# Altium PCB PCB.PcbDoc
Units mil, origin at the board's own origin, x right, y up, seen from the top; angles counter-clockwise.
Board outline 2500.28 x 2690 mil, 4 copper layers (Top Layer, GND, Power, Bottom Layer), stack 79.834 mil thick; 90 components, 42 nets, 225 pads, 112 vias.
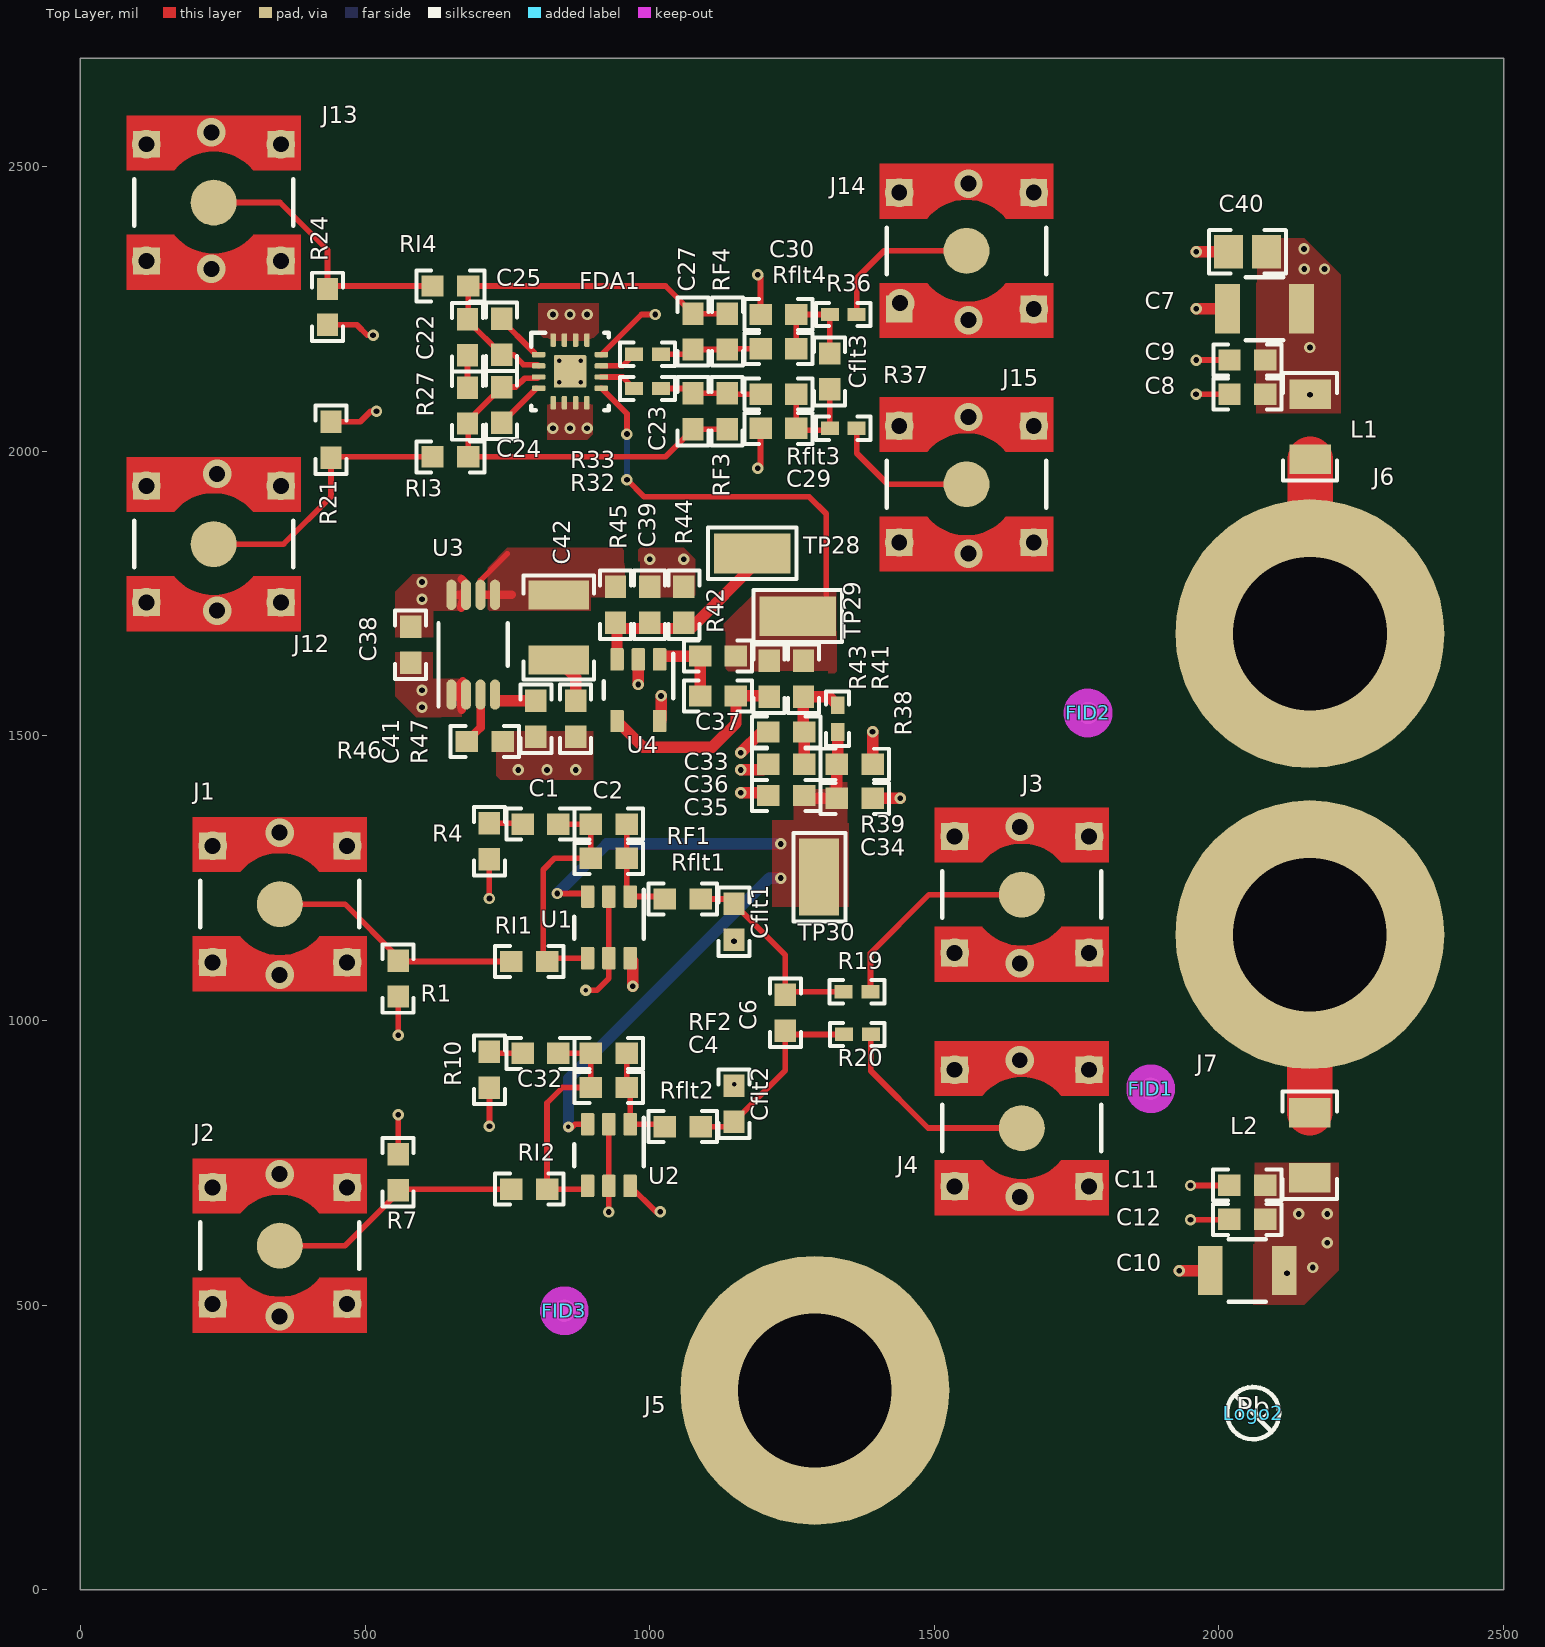
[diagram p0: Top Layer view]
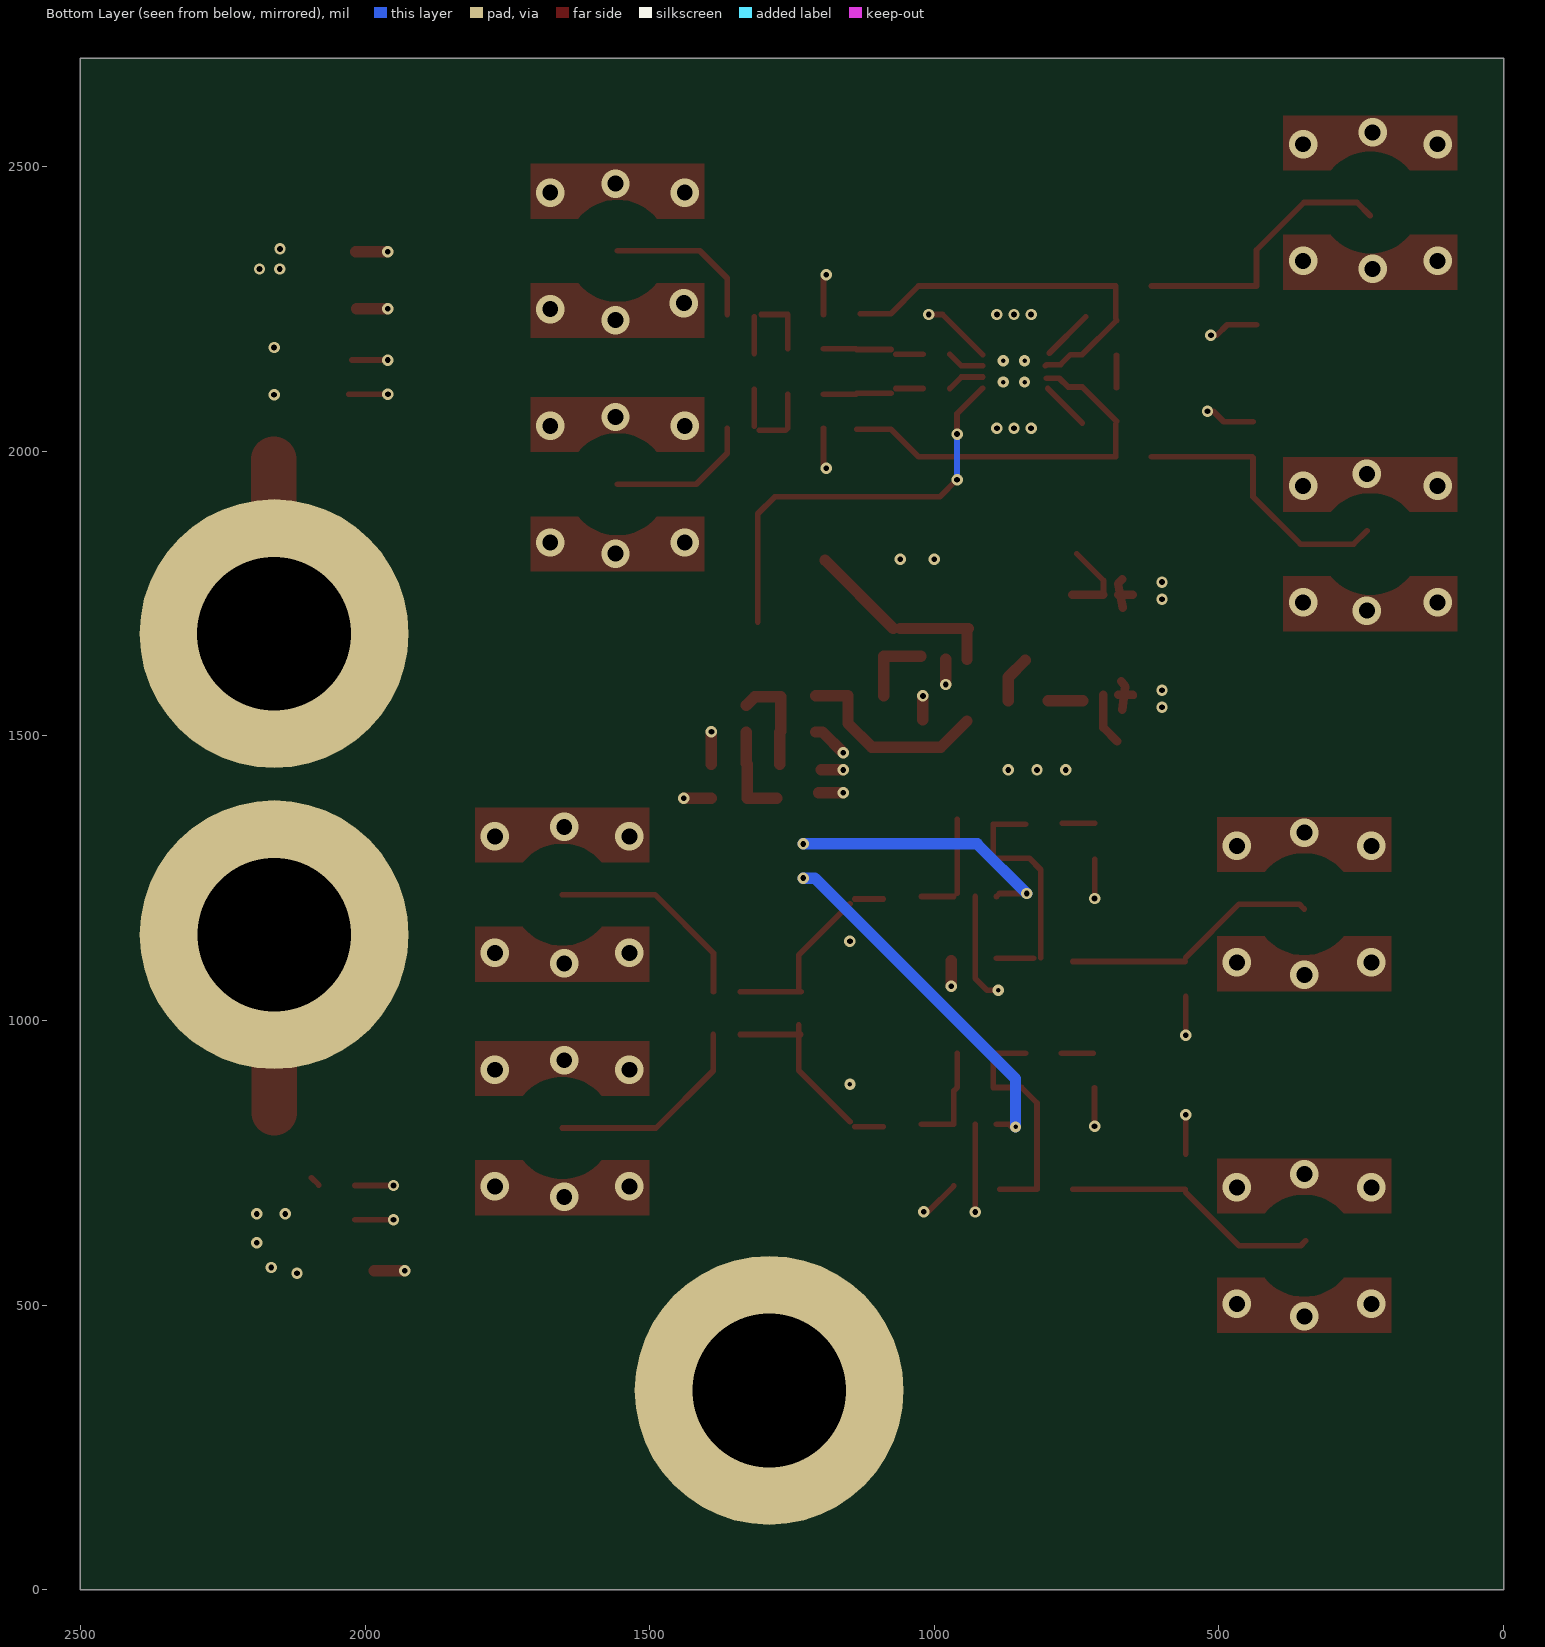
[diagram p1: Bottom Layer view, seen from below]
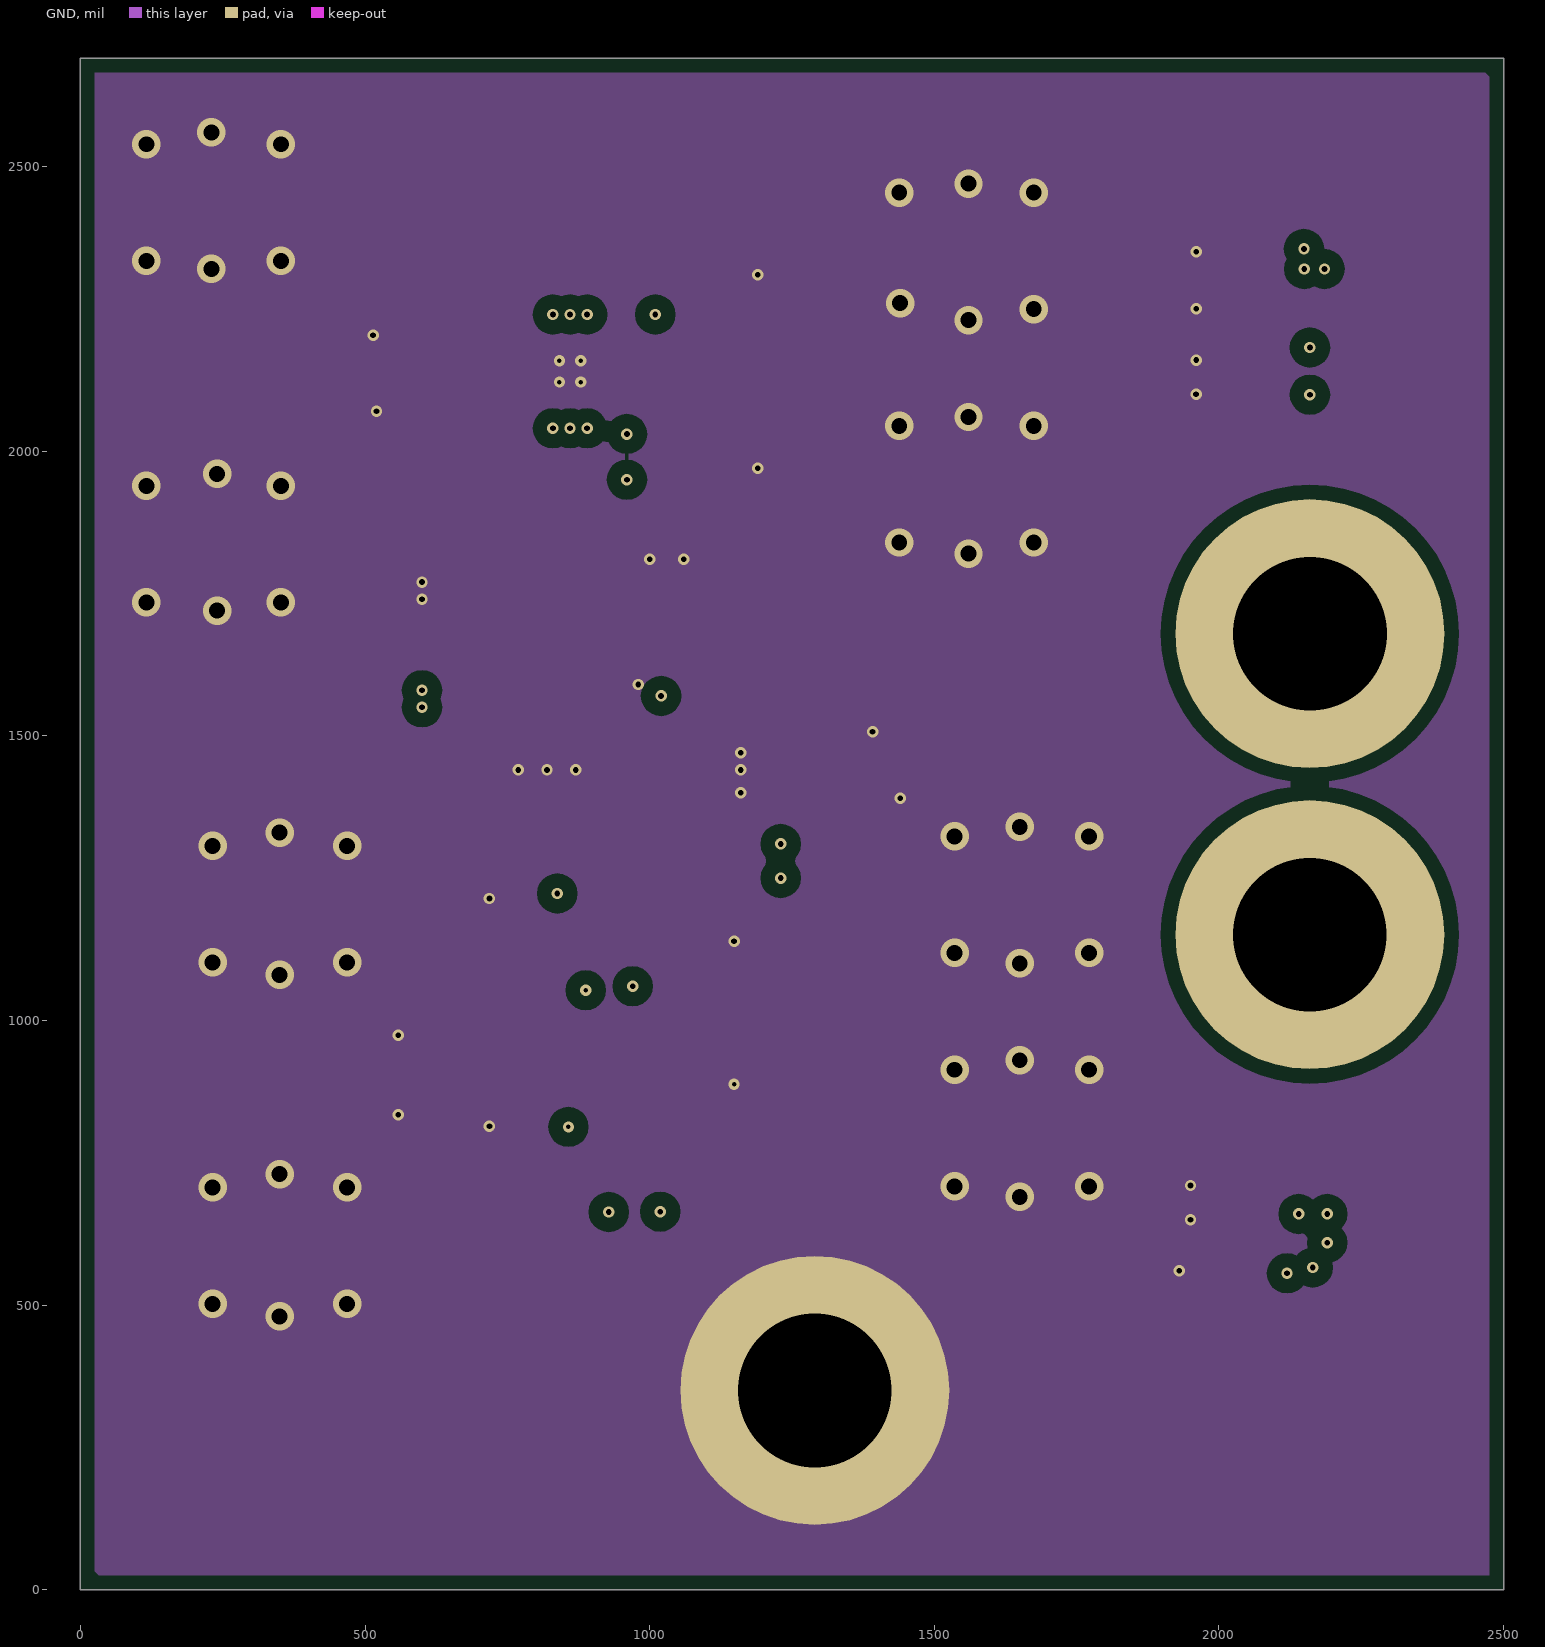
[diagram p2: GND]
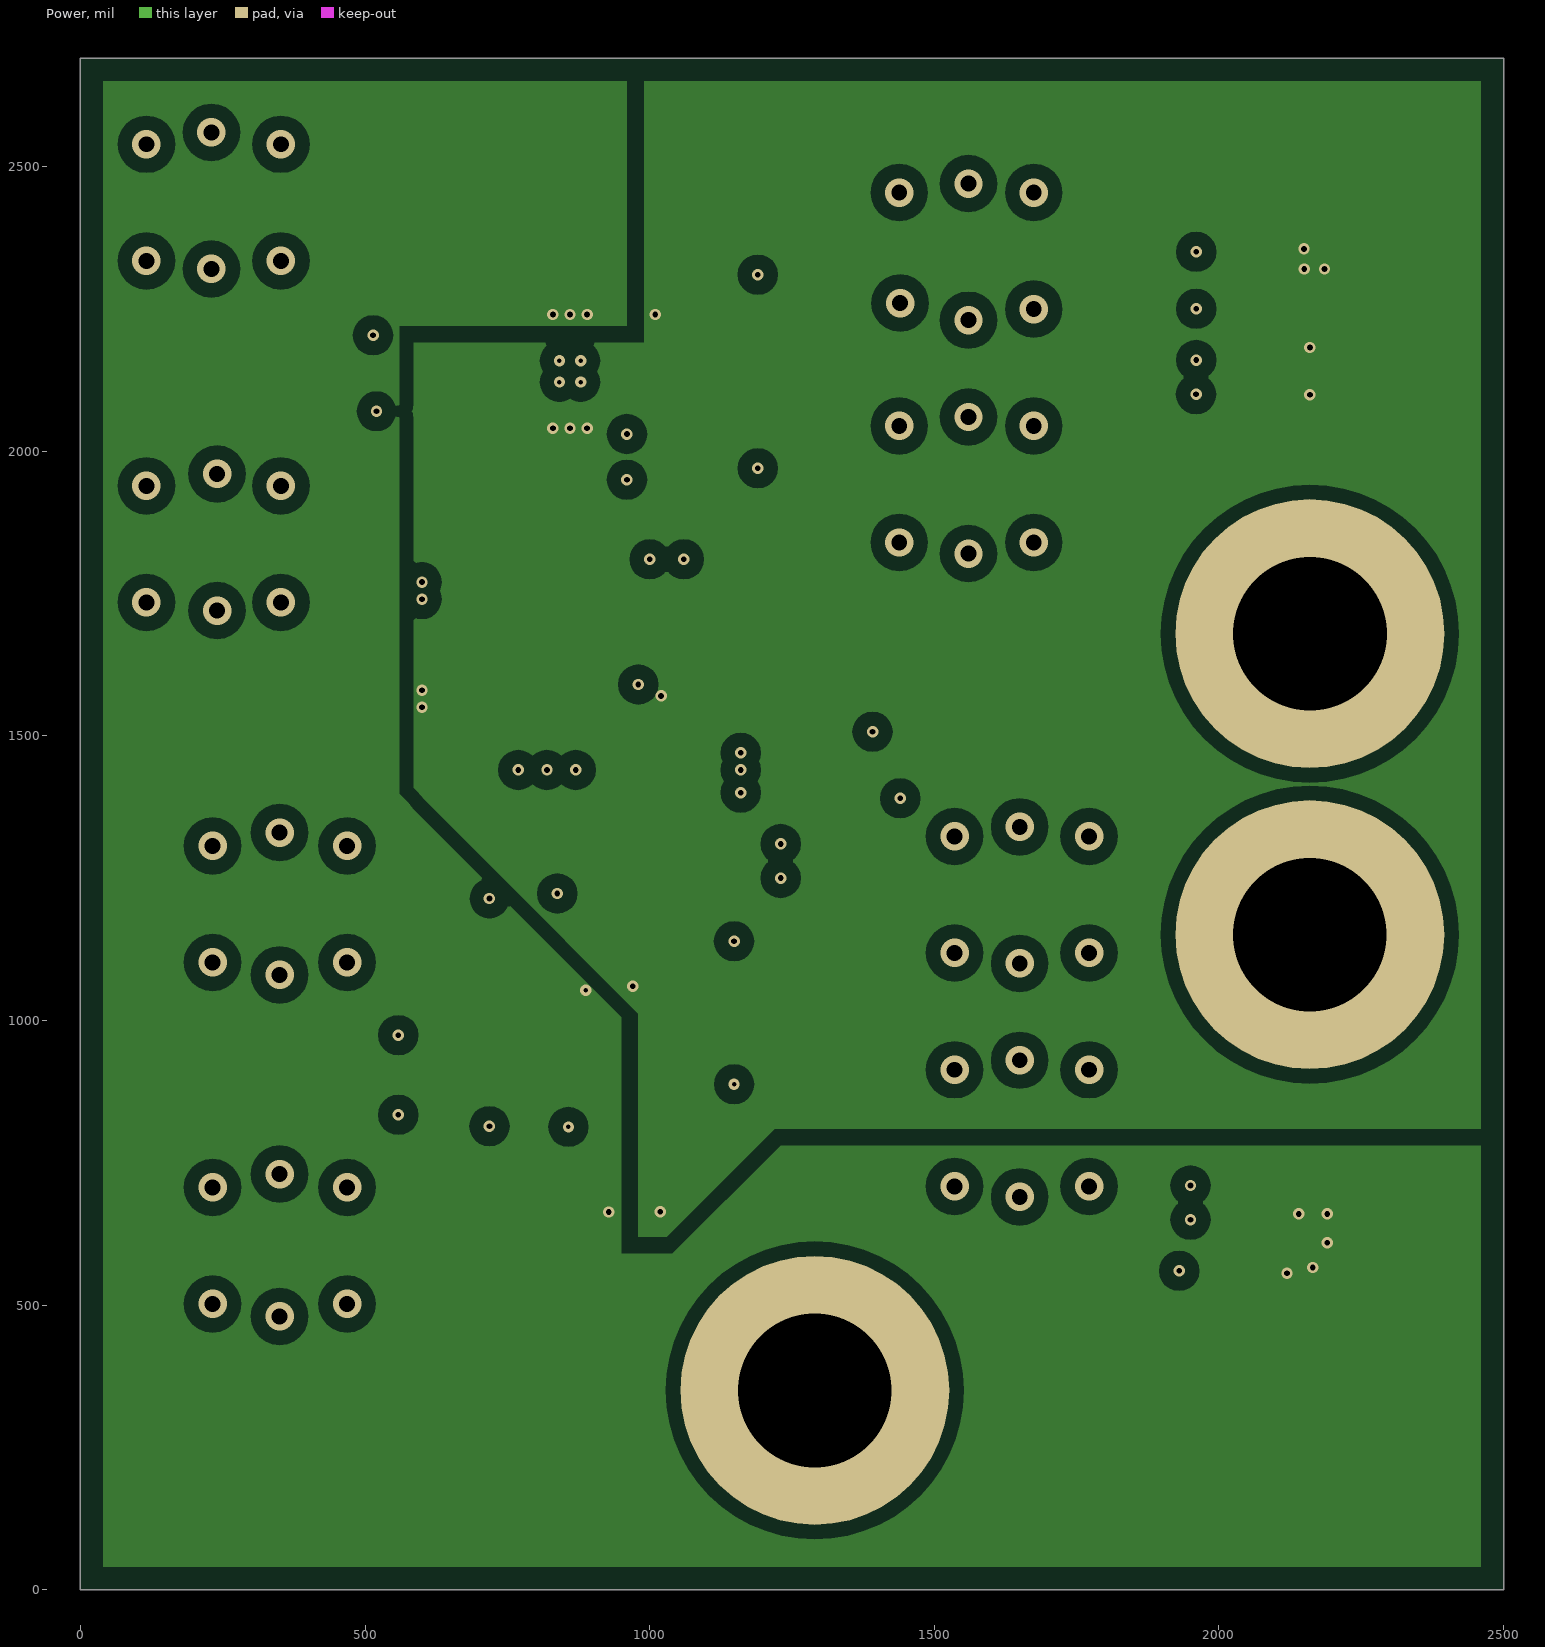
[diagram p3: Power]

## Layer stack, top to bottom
Top Solder: solder mask 0.4, Solder Resist, Dk 3.5
Top Layer: signal copper 1.4
Dielectric1: core 59.2, FR-4, Dk 4.8
GND: signal copper 1.417
Dielectric 3: prepreg 5, Dk 4.2
Power: signal copper 1.417
Dielectric 2: core 10, Dk 4.2
Bottom Layer: signal copper 1.4
Bottom Solder: solder mask 0.4, Solder Resist, Dk 3.5

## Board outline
-0.18,0 2499.89,0 2500.1,2690 0.05,2690

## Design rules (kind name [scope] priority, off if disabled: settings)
AcuteAngle [All] p1: minimum=4.50000000000000E+0001 checktracksonly=FALSE
AssemblyTestPointUsage [All] p1: valid=2
BoardOutlineClearance BoardOutlineClearance_MountingHoles [OnCopper and InComponentClass('Mounting Holes')] p1: gap=40
BoardOutlineClearance BoardOutlineClearance_Poly [OnCopper and IsPoly] p2: gap=25
BoardOutlineClearance [OnCopper and Not InComponentClass('Logo') and not InComponentClass('FiducialMark') and not InRegion(1000,500,4000,800) and not InPoly] p3: gap=75
Clearance Clearance_Keepouts [((IsTrack Or IsArc) And Not InPoly) And IsFree and IsKeepOut vs ((IsTrack Or IsArc) And Not InPoly) And IsFree and IsKeepOut] p1: gap=0
Clearance Clearance_Poly [InPolygon] p2: gap=25
Clearance [All] p3: gap=7.87
ComponentClearance ComponentClearance_MountingHoles_FiducialMarks [InComponentClass('Mounting Holes') vs InComponentClass('FiducialMark')] p1: gap=50 collisioncheckmode=3 verticalgap=10 showdistances=FALSE
ComponentClearance ComponentClearance_Shunt [InComponentClass('Header') vs InComponentClass('Shunt')] p2: gap=0 collisioncheckmode=3 verticalgap=0 showdistances=FALSE
ComponentClearance ComponentClearance_Logo [InComponentClass('Logo')] p3: gap=50 collisioncheckmode=3 verticalgap=10 showdistances=FALSE
ComponentClearance ComponentClearance_ScrewToNut [(HasFootprint('NY PMS 440 0025 PH')) vs (HasFootprint('Keystone_1902C'))] p4: gap=5 collisioncheckmode=3 verticalgap=10 showdistances=FALSE
ComponentClearance ComponentClearance_MountingHoles [InComponentClass('Mounting Holes')] p5: gap=250 collisioncheckmode=3 verticalgap=100000 showdistances=FALSE
ComponentClearance ComponentClearance_SmallPassives [HasFootprint('0201*') or HasFootprint('0402*') or HasFootprint('0508') or HasFootprint('0603*') or HasFootprint('0612') or HasFootprint('0805*') or HasFootprint('0815*') or HasFootprint('0830*') or HasFootprint('1206*') or HasFootprint('1210*') or HasFootprint('1808*') or HasFootprint('1812*') or HasFootprint('1825*') or HasFootprint('2010*') or HasFootprint('2220*') or HasFootprint('2225*') or HasFootprint('2512*') or HasFootprint('2728*') or HasFootprint('3518*') vs HasFootprint('0201*') or HasFootprint('0402*') or HasFootprint('0508') or HasFootprint('0603*') or HasFootprint('0612') or HasFootprint('0805*') or HasFootprint('0815*') or HasFootprint('0830*') or HasFootprint('1206*') or HasFootprint('1210*') or HasFootprint('1808*') or HasFootprint('1812*') or HasFootprint('1825*') or HasFootprint('2010*') or HasFootprint('2220*') or HasFootprint('2225*') or HasFootprint('2512*') or HasFootprint('2728*') or HasFootprint('3518*')] p6: gap=14.96 collisioncheckmode=3 verticalgap=10 showdistances=FALSE
ComponentClearance ComponentClearance_THtoSMT [IsThruComponent vs IsSMTComponent] p7: gap=40 collisioncheckmode=3 verticalgap=30 showdistances=FALSE
ComponentClearance ComponentClearance_THtoTH [IsThruComponent vs IsThruComponent] p8: gap=30 collisioncheckmode=3 verticalgap=30 showdistances=FALSE
ComponentClearance [All] p9: gap=30 collisioncheckmode=3 verticalgap=10 showdistances=FALSE
DiffPairsRouting [All] p1: maxlimit=100 minlimit=10 mostfreqgap=10 toplayer_minwidth=15 toplayer_maxwidth=15 toplayer_prefwidth=15 midlayer1_minwidth=15 midlayer1_maxwidth=15 midlayer1_prefwidth=15 midlayer2_minwidth=15 midlayer2_maxwidth=15 midlayer2_prefwidth=15 bottomlayer_minwidth=15 bottomlayer_maxwidth=15 bottomlayer_prefwidth=15 maxuncoupledlength=1000
FabricationTestPointUsage TestPointUsage [All] p1: valid=2 allowmultiple=FALSE
FabricationTestpoint Testpoint [All] p1: side=3 testpointundercomponent=TRUE minsize=40 maxsize=100 preferedsize=60 minholesize=0 maxholesize=40 preferedholesize=32 testpointgrid=1 allowsidetop=TRUE allowsidebottom=TRUE usegrid=TRUE gridtolerance=0.01
FanoutControl Fanout_LCC [IsLCC] p1: bgadir=Out bgaviamode=Centered fanoutstyle=Auto fanoutdirection=Alternating viagrid=1 // Fanout_LCC (Default Rule)
FanoutControl Fanout_BGA [IsBGA] p2: bgadir=Out bgaviamode=Centered fanoutstyle=Auto fanoutdirection=Alternating viagrid=1 // Fanout_BGA (Default Rule)
FanoutControl Fanout_Default [All] p4: bgadir=Out bgaviamode=Centered fanoutstyle=Auto fanoutdirection=Alternating viagrid=1 // Fanout_Default (Default Rule)
FanoutControl Fanout_Small [(CompPinCount < 5)] p5: bgadir=Out bgaviamode=Centered fanoutstyle=Auto fanoutdirection=OutThenIn viagrid=1 // Fanout_Small (Default Rule)
HoleSize [All] p1: absolutevalues=TRUE maxlimit=280 minlimit=5 maxpercent=80.000 minpercent=20.000
MinimumAnnularRing MinimumAnnularRing_ThermalPadVias [IsVia and InAnyComponent] p1: minimumring=5.91
MinimumAnnularRing [All] p2: minimumring=5
MinimumSolderMaskSliver MinimumSolderMaskSliver_Logo [InComponentClass('Logo') vs InComponentClass('Logo')] p1: minsoldermaskwidth=0.7
MinimumSolderMaskSliver [All] p2: minsoldermaskwidth=3.94
PlaneConnect [All] p1: planeconnectstyle=Relief reliefexpansion=10 reliefentries=4 reliefconductorwidth=10 reliefairgap=10
PolygonConnect PolygonConnect_10 [All vs IsNamedPolygon('GND')] p1: connectstyle=Direct reliefconductorwidth=10 reliefentries=4 polygonreliefangle="90 Angle" airgapwidth=10
PolygonConnect PolygonConnect_9 [All] p2: connectstyle=Direct reliefconductorwidth=10 reliefentries=4 polygonreliefangle="90 Angle" airgapwidth=10
PolygonConnect PolygonConnect_8 [All vs IsNamedPolygon('GND')] p3: connectstyle=Direct reliefconductorwidth=10 reliefentries=4 polygonreliefangle="90 Angle" airgapwidth=10
PolygonConnect PolygonConnect_7 [All vs IsNamedPolygon('GND')] p4: connectstyle=Direct reliefconductorwidth=10 reliefentries=4 polygonreliefangle="90 Angle" airgapwidth=10
PolygonConnect PolygonConnect_6 [All vs IsNamedPolygon('GND')] p5: connectstyle=Direct reliefconductorwidth=10 reliefentries=4 polygonreliefangle="90 Angle" airgapwidth=10
PolygonConnect PolygonConnect_5 [All vs IsNamedPolygon('GND')] p6: connectstyle=Direct reliefconductorwidth=10 reliefentries=4 polygonreliefangle="90 Angle" airgapwidth=10
PolygonConnect PolygonConnect_4 [All vs IsNamedPolygon('GND')] p7: connectstyle=Direct reliefconductorwidth=10 reliefentries=4 polygonreliefangle="90 Angle" airgapwidth=10
PolygonConnect PolygonConnect_3 [All vs IsNamedPolygon('GND')] p8: connectstyle=Direct reliefconductorwidth=10 reliefentries=4 polygonreliefangle="90 Angle" airgapwidth=10
PolygonConnect PolygonConnect_2 [All vs IsNamedPolygon('GND')] p9: connectstyle=Direct reliefconductorwidth=10 reliefentries=4 polygonreliefangle="90 Angle" airgapwidth=10
PolygonConnect PolygonConnect_1 [All vs IsNamedPolygon('GND')] p10: connectstyle=Direct reliefconductorwidth=10 reliefentries=4 polygonreliefangle="90 Angle" airgapwidth=10
PolygonConnect [All] p11: connectstyle=Relief reliefconductorwidth=10 reliefentries=4 polygonreliefangle="90 Angle" airgapwidth=10
RoutingVias ThermalPadVias [IsVia and InAnyComponent] p1: holewidth=7.87 width=19.68 viastyle="Through Hole" minholewidth=7.87 minwidth=19.68 maxholewidth=12.99 maxwidth=23.62
RoutingVias [All] p2: holewidth=16 width=34 viastyle="Through Hole" minholewidth=5 minwidth=6 maxholewidth=40 maxwidth=65
SilkToBoardRegionClearance [Not ((IsComment or IsDesignator) And (Hide <> 'False')) and not InRegion(1000,500,4000,800)] p1:
SilkToSilkClearance SilkToSilkClearance_Pb-FreeLogo [(HasFootprint('Pb-Free_Overlay_Medium') OR HasFootprint('Pb-Free_Overlay_Small')) vs (HasFootprint('Pb-Free_Overlay_Medium') OR HasFootprint('Pb-Free_Overlay_Small'))] p1: silktosilkclearance=0
SilkToSilkClearance [All] p2: silktosilkclearance=4
SilkToSolderMaskClearance SilkToComponentPadClearance [IsPad and InAnycomponent] p1: minsilkscreentomaskgap=5 clearancetoexposedcopper=TRUE
SilkToSolderMaskClearance "Silk to Solder Mask Opening" [All] p2: minsilkscreentomaskgap=4 clearancetoexposedcopper=FALSE
SolderMaskExpansion [All] p1: expansion=1.97
Width [All] p1: maxlimit=100 minlimit=6 preferedwidth=10 checkconnectedcopper=TRUE
15 further rules are at their usual default settings.

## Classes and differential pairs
component class OPA625_VCA_Disto_Hardware: C1 C2 C4 C6 C7 C8 C9 C10 C11 C12 C32 C33 C34 C35 C36 C37 C38 C39 C40 C41 C42 Cflt1 Cflt2 FID1 FID2 FID3 J1 J2 J3 J4 J5 J6 J7 L1 L2 Logo2 R1 R4 R7 R10 R19 R20 R38 R39 R41 R42 R43 R44 R45 R46 R47 RF1 RF2 Rflt1 Rflt2 RI1 RI2 TP28 TP29 TP30 U1 U2 U3 U4
component class FiducialMark: FID1 FID2 FID3
component class THS4551_VCA_Disto_Hardware: C22 C23 C24 C25 C27 C29 C30 Cflt3 FDA1 J12 J13 J14 J15 R21 R24 R27 R32 R33 R36 R37 RF3 RF4 Rflt3 Rflt4 RI3 RI4

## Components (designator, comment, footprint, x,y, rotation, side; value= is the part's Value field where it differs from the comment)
C1 "GRM1885C2A131JA01D" 0603 808.19,1344.7 r0 top
C2 "GRM1885C2A5R0CA01D" 0603 928.19,1344.7 r180 top
C4 "GRM1885C2A5R0CA01D" 0603 928.19,882.11 r180 top
C6 "C1608C0G2A102J080AA" 0603 1238.19,1013.41 r270 top
C7 "UMK325AB7106KM-T" 1210_280 2080,2250 r180 top
C8 "GRM188R72A104KA35D" 0603 2050,2100 r180 top
C9 "GRM188R71E103KA01D" 0603 2050,2160 r180 top
C10 "UMK325AB7106KM-T" 1210_280 2049.65,560.57 r180 top
C11 "GRM188R72A104KA35D" 0603 2049.65,710.57 r180 top
C12 "GRM188R71E103KA01D" 0603 2049.65,650.57 r180 top
C22 "GRM1885C2A680JA01D" 0603 680,2200 r90 top
C23 "GRM1885C2A5R0CA01D" 0603 1076.2,2070 r270 top
C24 "C1608C0G2A102J080AA" 0603 740,2081.02 r90 top
C25 "C1608C0G2A102J080AA" 0603 740,2201.02 r270 top
C27 "GRM1885C2A5R0CA01D" 0603 1076.2,2210 r90 top
C29 "C1608C0G2A102J080AA" 0603 1226.2,2040 r180 top
C30 "C1608C0G2A102J080AA" 0603 1226.2,2240 r180 top
C32 "GRM1885C2A131JA01D" 0603 808.19,942.11 r0 top
C33 "C0603C104J3RACTU" 0603 1240,1506.64 r180 top
C34 "C0603C102J5GAC" 0603 1360,1390 r0 top
C35 "C0603C102J5GAC" 0603 1240,1394.96 r180 top
C36 "GRM188R71E105KA12D" 0603 1240,1450 r180 top
C37 "GRM188R71E105KA12D" 0603 1120,1570 r0 top
C38 "C0603C104J3RACTU" 0603 580,1660 r270 top
C39 "GRM188R71E105KA12D" 0603 1000,1730 r90 top
C40 "GRM21BR71A106KE51L" 0805 2050,2350 r0 top
C41 "GRM188R71A105KA61D" 0603 800,1530 r270 top
C42 "GRM32ER71A476KE15L" 1210_270 840,1690 r270 top
Cflt1 "C1608C0G2A102J080AA" 0603 1148.19,1173.41 r270 top
Cflt2 "C1608C0G2A102J080AA" 0603 1148.19,853.41 r90 top
Cflt3 "C1608C0G2A102J080AA" 0603 1316.2,2140 r90 top
FDA1 "THS4551IRGTR" RGT0016A 860,2140 r0 top
FID1 "Fiducial" Fiducial10-20 1880,880 r180 top
FID2 "Fiducial" Fiducial10-20 1770,1540 r0 top
FID3 "Fiducial" Fiducial10-20 850,490 r90 top
J1 "CONSMA001-SMD-G" Linx_CONSMA001-SMD-G 350.31,1204.21 r90 top
J2 "CONSMA001-SMD-G" Linx_CONSMA001-SMD-G 350.31,604.21 r90 top
J3 "CONSMA001-SMD-G" Linx_CONSMA001-SMD-G 1653.64,1220.89 r90 top
J4 "CONSMA001-SMD-G" Linx_CONSMA001-SMD-G 1653.64,810.89 r90 top
J5 "6095" Keystone_6095 1290,350 r0 top
J6 "6095" Keystone_6095 2159.76,1679.29 r0 top
J7 "6095" Keystone_6095 2159.65,1150.57 r180 top
J12 "CONSMA001-SMD-G" Linx_CONSMA001-SMD-G 234.01,1836.69 r270 top
J13 "CONSMA001-SMD-G" Linx_CONSMA001-SMD-G 234.01,2436.69 r90 top locked
J14 "CONSMA001-SMD-G" Linx_CONSMA001-SMD-G 1556.51,2351.87 r90 top
J15 "CONSMA001-SMD-G" Linx_CONSMA001-SMD-G 1556.51,1941.87 r90 top
L1 "MI1206K310R-10" 1206 2160,2042.76 r90 top
L2 "MI1206K310R-10" 1206 2159.65,780.57 r270 top
Logo2 "Pb-Free Symbol" Pb-Free_Overlay_Small 2060,310 r0 top
R1 "RC0603FR-0752R3L" 0603 558.19,1073.41 r270 top
R4 "RC0603FR-07124RL" 0603 718.19,1314.7 r90 top
R7 "RC0603FR-0752R3L" 0603 558.19,733.41 r90 top
R10 "RC0603FR-07124RL" 0603 718.19,913.41 r90 top
R19 "ERJ-2GE0R00X" 0402 1364.23,1050.56 r0 top
R20 "ERJ-2GE0R00X" 0402 1364.74,975.33 r0 top
R21 "RC0603FR-0752R3L" 0603 440,2020 r90 top
R24 "RC0603FR-0752R3L" 0603 434.01,2253.39 r270 top
R27 "CRCW0603249RFKEA" 0603 680,2080 r270 top
R32 "ERJ-2GE0R00X" 0402 996.2,2110 r0 top
R33 "ERJ-2GE0R00X" 0402 996.2,2170 r0 top
R36 "ERJ-2GE0R00X" 0402 1340,2240 r0 top
R37 "ERJ-2GE0R00X" 0402 1340,2040 r0 top
R38 "ERJ-2GE0R00X" 0402 1330,1530 r270 top
R39 "RT0603BRB071KL" 0603 1360,1450 r180 top
R41 "RT0603BRB071KL" 0603 1270,1600 r90 top
R42 "RG1608P-4990-B-T5" 0603 1120,1640 r0 top
R43 "RG1608P-203-B-T5" 0603 1210,1600 r90 top
R44 "RG1608P-4992-B-T5" 0603 1060,1730 r270 top
R45 "RG1608P-4992-B-T5" 0603 940,1730 r90 top
R46 "ERJ-3RQFR22V" 0603 710,1490 r180 top
R47 "ERJ-3RQFR22V" 0603 870,1530 r270 top
RF1 "RT0603BRB071KL" 0603 928.19,1284.7 r0 top
RF2 "RT0603BRB071KL" 0603 928.19,942.11 r0 top
RF3 "RT0603BRB071KL" 0603 1136.2,2070 r90 top
RF4 "RT0603BRB071KL" 0603 1136.2,2210 r270 top
Rflt1 "RT0603BRD0720RL" 0603 1058.19,1213.41 r0 top
Rflt2 "RT0603BRD0720RL" 0603 1058.19,813.41 r0 top
Rflt3 "RT0603BRD0720RL" 0603 1226.2,2100 r0 top
Rflt4 "RT0603BRD0720RL" 0603 1226.2,2180 r0 top
RI1 "RT0603BRB071KL" 0603 788.19,1103.41 r0 top
RI2 "RT0603BRB071KL" 0603 788.19,703.41 r0 top
RI3 "RT0603BRB071KL" 0603 650,1990 r0 top
RI4 "RT0603BRB071KL" 0603 650,2290 r0 top
TP28 "5015" Testpoint_Keystone_Miniature 1180,1820 r180 top
TP29 "5015" Testpoint_Keystone_Miniature 1260,1710 r180 top
TP30 "5015" Testpoint_Keystone_Miniature 1297.59,1251.61 r90 top
U1 "OPA625IDBVR" DBV0006A_N 928.19,1163.41 r270 top
U2 "OPA625IDBVR" DBV0006A_N 928.19,763.41 r270 top
U3 "REF6050IDGKR" DGK0008A_N 690,1660 r90 top
U4 "OPA376AIDBVR" DBV0005A_N 980,1580 r270 top

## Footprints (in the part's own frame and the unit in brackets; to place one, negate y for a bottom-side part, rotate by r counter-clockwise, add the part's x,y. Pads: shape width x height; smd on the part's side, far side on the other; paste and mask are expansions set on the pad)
0402 [mm] "0402 from SM-752 data"
  rect 0.8x0.6 smd: 1(-0.6,0) 2(0.6,0)
  silkscreen extent -1.22,-0.52 1.22,0.52, body extent -0.55,-0.3 0.55,0.3, height 0.6
0603 [mm] "0603 from SM-752 data"
  rect 1x0.95 smd: 1(-0.8,0) 2(0.8,0)
  silkscreen extent -1.52,-0.69 1.52,0.69, body extent -0.87,-0.47 0.87,0.47, height 1
0805 [mm] "0805 from SM-752 data"
  rect 1.3x1.5 smd: 1(-0.85,0) 2(0.85,0)
  silkscreen extent -1.72,-0.97 1.72,0.97, body extent -1.1,-0.72 1.1,0.72, height 1.45
1206 [mm] "1206 from SM-752 data"
  rect 1.3x1.85 smd: 1(-1.45,0) 2(1.45,0)
  silkscreen extent -2.4,-1.21 2.4,1.21, body extent -1.7,-0.9 1.7,0.9, height 1.35
1210_270 [mm] "1210"
  rect 1.3x2.7 smd: 1(-1.45,0) 2(1.45,0)
  silkscreen extent -2.32,-1.57 2.32,1.57, body extent -1.7,-1.35 1.7,1.35, height 2.7
1210_280 [mm] "SMD, 2-Leads, Body 3.6x2.8mm, Height 2.8mm"
  rect 1.1x2.2 smd: 1(-1.65,0) 2(1.65,0)
  silkscreen extent -0.84,-1.4 0.84,1.4, body extent -1.8,-1.4 1.8,1.4, height 2.8
DBV0005A_N [mm] "SOT23, 5-Leads, Body 2.9x1.6mm, Pitch 0.95mm, Lead Span 2.8mm, IPC Medium Density"
  rrect17% 1x0.6 smd: 1(-1.375,0.95) 2(-1.375,0) 3(-1.375,-0.95) 4(1.375,-0.95) 5(1.375,0.95)
  silkscreen extent -1.63,-1.55 0.38,1.55, body extent -1.42,-1.46 1.42,1.46, height 1.09
DBV0006A_N [mm] "SOT23, 6-Leads, Body 2.9x1.6mm, Pitch 0.95mm, Lead Span 2.8mm, IPC Medium Density"
  rrect17% 1x0.6 smd: 1(-1.375,0.95) 2(-1.375,0) 3(-1.375,-0.95) 4(1.375,-0.95) 5(1.375,0) 6(1.375,0.95)
  silkscreen extent -1.68,-1.55 0.5,1.55, body extent -1.42,-1.46 1.42,1.46, height 1.12
DGK0008A_N [mm] "TSOP, 8-Leads, Body 3x3mm, Pitch 0.65mm, IPC Medium Density"
  oval 1.35x0.45 smd: 1(-2.225,0.975) 2(-2.225,0.325) 3(-2.225,-0.325) 4(-2.225,-0.975) 5(2.225,-0.975) 6(2.225,-0.325) 7(2.225,0.325) 8(2.225,0.975)
  silkscreen extent -2.75,-1.55 0.95,1.55, body extent -2.45,-1.5 2.45,1.5, height 0.96
Fiducial10-20 [mm]
  round 1 smd mask+0.5: 1(0,0)
  Top Layer keep-out circle w1.178: c0,0 r0.5
Keystone_6095 [mm] "Banana Jack Uninsulated Standard Type"
  round 12 hole 6.858: 1(0,0)
  body extent -4.77,-5.5 4.75,5.49, height 2.39
Linx_CONSMA001-SMD-G [mm] "SMD, 5-Leads, Body 7x7mm, Height 10.5mm"
  round 2.05 smd: 1(0,0)
  rect 1.2x1.2 smd: 2(-2.6,-3) 3(2.6,-3) 4(2.6,3) 5(-2.6,3)
  Top Layer region: 3.88,-3.88 1.44,-3.88 1.44,-1.761 1.448,-1.761 2.062,-0.974 2.28,0 2.062,0.974 1.448,1.761 1.448,1.761 1.44,1.761 1.44,3.88 3.88,3.88
  Top Layer region: -3.88,-3.88 -1.44,-3.88 -1.44,-1.761 -1.448,-1.761 -2.062,-0.974 -2.28,0 -2.062,0.974 -1.448,1.761 -1.448,1.761 -1.44,1.761 -1.44,3.88 -3.88,3.88
  silkscreen extent -1.04,-3.55 1.04,3.55, body extent -3.55,-3.55 3.55,3.55, height 10.5
Pb-Free_Overlay_Small [mil]
  silkscreen extent -46,-46 46,46
RGT0016A [mm] "QFN, 16-Leads, Body 3x3mm, Pitch 0.5mm, Thermal Pad 1.45x1.45mm, TI Recommended"
  rrect42% 0.6x0.24 smd: 1(-1.4,0.75) 2(-1.4,0.25) 3(-1.4,-0.25) 4(-1.4,-0.75) 9(1.4,-0.75) 10(1.4,-0.25) 11(1.4,0.25) 12(1.4,0.75)
  rrect42% 0.24x0.6 smd: 5(-0.75,-1.4) 6(-0.25,-1.4) 7(0.25,-1.4) 8(0.75,-1.4) 13(0.75,1.4) 14(0.25,1.4) 15(-0.25,1.4) 16(-0.75,1.4)
  rrect7% 1.45x1.45 smd paste-0.725: 17(0,0)
  silkscreen extent -1.72,-1.73 1.72,1.73, body extent -1.57,-1.57 1.58,1.58, height 1.01
Testpoint_Keystone_Miniature [mil] "Miniature SMT test point"
  rect 135x70 smd: 1(0,0)
  silkscreen extent -78,-46 78,45, body extent -52,-20 52,20, height 61

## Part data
C1 C32: "CAP, CERM, 130 pF, 100 V, +/- 5%, C0G/NP0, 0603"
C2 C4 C23 C27: "CAP, CERM, 5 pF, 100 V, +/- 5%, C0G/NP0, 0603"
C6 C24 C25 C29 C30 Cflt1 Cflt2 Cflt3: "CAP, CERM, 1000 pF, 100 V, +/- 5%, C0G/NP0, 0603"
C7 C10: "CAP, CERM, 10 µF, 50 V, +/- 10%, X7R, 1210"
C8 C11: "CAP, CERM, 0.1 µF, 100 V, +/- 10%, X7R, 0603"
C9 C12: "CAP, CERM, 0.01 µF, 25 V, +/- 10%, X7R, 0603"
C22: "CAP, CERM, 68 pF, 100 V, +/- 5%, C0G/NP0, 0603"
C33 C38: "CAP, CERM, 0.1 µF, 25 V, +/- 5%, X7R, 0603"
C34 C35: "CAP, CERM, 1000 pF, 50 V, +/- 5%, C0G/NP0, 0603"
C36 C37 C39: "CAP, CERM, 1 µF, 25 V, +/- 10%, X7R, 0603"
C40: "CAP, CERM, 10uF, 10V, +/-10%, X7R, 0805"
C41: "CAP, CERM, 1uF, 10V, +/-10%, X7R, 0603"
C42: "CAP, CERM, 47 µF, 10 V, +/- 10%, X7R, 1210"
FDA1: "Low Power, Precision, 160MHz, Fully Differential Amplifier, RGT0016A"
FID1 FID2 FID3: "Fiducial mark.  There is nothing to buy or mount."
J1 J2 J3 J4 J12 J13 J14 J15: "Jack, SMA, PCB, Gold, SMT"
J5 J6 J7: "Standard Banana Jack, Uninsulated"
L1 L2: "Ferrite Bead, 31 ohm @ 100 MHz, 1.5 A, 1206"
Logo2: library part Pb-Free
R1 R7 R21 R24: "RES, 52.3, 1%, 0.1 W, 0603"
R4 R10: "RES, 124, 1%, 0.1 W, 0603"
R19 R20 R32 R33 R36 R37 R38: "RES, 0, 5%, 0.063 W, 0402"
R27: "RES, 249, 1%, 0.1 W, 0603"
R39 R41 RF1 RF2 RF3 RF4 RI1 RI2 RI3 RI4: "RES, 1.00 k, 0.1%, 0.1 W, 0603"
R42: "RES, 499, 0.1%, 0.1 W, 0603"
R43: "RES, 20.0 k, 0.1%, 0.1 W, 0603"
R44 R45: "RES, 49.9 k, 0.1%, 0.1 W, 0603"
R46 R47: "RES, 0.22 ohm, 1%, 0.1W, 0603"
Rflt1 Rflt2 Rflt3 Rflt4: "RES, 20.0, 0.1%, 0.1 W, 0603"
TP28 TP29 TP30: "Test Point, Miniature, SMT"
U1 U2: "High Bandwidth, High Precision, Low Noise and Distortion Amplifier with Ultra-Fast Transition time Low Power mode, DBV0006A (SOT-6)"
U3: "High-Precision Voltage Reference with Integrated High-Bandwidth Buffer, DGK0008A (VSSOP-8)"
U4: "Precision, Low Noise, Low Iq Operational Amplifier, 2.2 to 5.5 V, -40 to 125 degC, 5-pin SOT23 (DBV0005A), Green (RoHS & no Sb/Br)"

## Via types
v1: diameter 20, hole 10, Top Layer to Bottom Layer, 57 vias
v2: diameter 50, hole 28, Top Layer to Bottom Layer, 48 vias
v3: diameter 19.68, hole 7.87, Top Layer to Bottom Layer, 7 vias

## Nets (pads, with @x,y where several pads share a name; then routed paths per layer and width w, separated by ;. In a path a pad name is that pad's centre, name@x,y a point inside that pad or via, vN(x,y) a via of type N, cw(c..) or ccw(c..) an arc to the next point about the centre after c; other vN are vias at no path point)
GND: C7.2 C8.2 C9.2 C10.2 C11.2 C12.2 C29.2 C30.2 C33.2 C34.2 C35.2 C36.2 C38.1 C39.2 C40.1 C41.2 Cflt1.2 Cflt2.2 FDA1.17 J1.2 J1.3 J1.4 J1.5 J2.2 J2.3 J2.4 J2.5 J3.2 J3.3 J3.4 J3.5 J4.2 J4.3 J4.4 J4.5 J5.1 J12.2 J12.3 J12.4 J12.5 J13.2 J13.3 J13.4 J13.5 J14.2 J14.3 J14.4 J14.5 J15.2 J15.3 J15.4 J15.5 R1.2 R4.1 R7.2 R10.1 R21.2 R24.2 R39.1 R44.1 R46.1 R47.2 U3.7 U3.8 U4.2 | length 1375.8
  Top Layer w10: R24.2 485.51,2221.89 504.01,2203.39 v1(514.01,2203.39) ; R21.2 491.5,2051.5 510,2070 v1(520,2070) ; v1@558.19,974.35 R1.2 ; R7.2@558.43,765.14 v1(558.43,834.11) ; 718.19,1224.35 R4.1 ; v1(718.43,814.11) R10.1@718.43,881.67 ; v1@1194.7,1974.7 C29.2 ; C30.2 v1@1194.7,2305.3 ; v1(1950,650) C12.2@2017.58,650 ; v1(1950,710) C11.2@2017.58,710 ; v1(1959.8,2100) C8.2@2028.74,2100 ; v1@1959.8,2160 C9.2@2022.74,2160
  Top Layer w15: U3.8 U3.7 ; 669.29,1725 677.2,1767.38 669.99,1774.6
  Top Layer w20: v1(980,1590) U4.2 ; v1(1160,1400) C35.2@1203.47,1400 ; v1(1160,1440) C36.2@1198.5,1440 ; v1(1160,1470) 1196.64,1506.64 C33.2 ; C34.2 v1(1440,1390) ; R39.1 v1(1391.5,1507.01) ; v1(1930,560) C10.2@1984.12,560 ; v1(1960,2250) C7.2 ; v1(1960,2350) C40.1
  other v1: 558.43,974.11 1148.19,1138.98 718.43,1214.11 769.14,1440 819.57,1440 870,1440 600,1740 600,1770 1000,1810 1060,1810 1190,1970 1960,2160 1190,2310
  other v2: 350,480 232.2,501.85 468.42,501.85 1650,690 232.2,706.57 468.42,706.57 1535.53,708.52 1771.75,708.52 350,730 1535.53,913.25 1771.75,913.25 1650,930 350,1080 1650,1100 232.2,1101.85 468.42,1101.85 1535.53,1118.52 1771.75,1118.52 232.2,1306.57 468.42,1306.57 1535.53,1323.25 1771.75,1323.25 350,1330 1650,1340 240,1720 115.9,1734.33 352.12,1734.33 1560,1820 1438.4,1839.51 1674.62,1839.51 115.9,1939.06 352.12,1939.06 240,1960 1438.4,2044.24 1674.62,2044.24 1560,2060 1560,2230 1674.62,2249.51 1440,2260 230,2320 115.9,2334.33 352.12,2334.33 1438.4,2454.23 1674.62,2454.23 1560,2470 115.9,2539.06 352.12,2539.06 230,2560
  other v3: 1148.19,887.85 841.3,2121.3 878.7,2121.3 841.3,2158.7 878.7,2158.7
NetC1_1: C1.1 R4.2 | length 57
  Top Layer w10: R4.2 C1.1@775.2,1346.2
NetC1_2: C1.2 C2.2 RF1.1 RI1.2 U1.4 | length 428.7
  Top Layer w10: RI1.2@812.84,1110.25 812.84,1264.55 833,1284.7 RF1.1 C2.2 C1.2 ; RI1.2@825.55,1109.27 U1.4
NetC2_1: C2.1 RF1.2 Rflt1.1 U1.1 | length 186.9
  Top Layer w10: U1.1@959.69,1223.44 C2.1 C2.1@959.69,1353.41 ; U1.1 Rflt1.1@1022.56,1217.54
NetC4_1: C4.1 RF2.2 Rflt2.1 U2.1 | length 184
  Top Layer w10: RF2.2 C4.1 965.59,876.2 U2.1 Rflt2.1@1022.56,817.54
NetC4_2: C4.2 C32.2 RF2.1 RI2.2 U2.4 | length 422
  Top Layer w10: C32.2 RF2.1 C4.2 846.89,882.11 819.69,854.9 RI2.2 U2.4@884.92,703.41
NetC6_1: C6.1 Cflt1.1 R19.1 Rflt1.2 | length 343.7
  Top Layer w10: Rflt1.2 Cflt1.1@1139.69,1213.41 ; Cflt1.1 1238.19,1114.9 C6.1@1238.19,1054.9 ; C6.1@1234.23,1050.56 R19.1
NetC6_2: C6.2 Cflt2.1 R20.1 Rflt2.2 | length 363.7
  Top Layer w10: Rflt2.2 Cflt2.1@1139.69,813.41 ; Cflt2.1 1238.19,911.91 C6.2 C6.2@1238.19,991.91 ; C6.2@1234.74,975.33 R20.1
NetC22_1: C22.1 R27.1 | length 57
  Top Layer w10: R27.1 C22.1
NetC22_2: C22.2 C25.2 C27.2 FDA1.2 RF4.1 RI4.2 | length 683.5
  Top Layer w10: C22.2@680,2229.53 C25.2 760.47,2169.53 778.07,2151.93 802.8,2151.93 FDA1.2 ; C22.2@681.5,2232.99 RI4.2 1027.7,2290 C27.2 RF4.1@1130,2241.5
NetC23_1: C23.1 R32.2 RF3.2 Rflt3.1 | length 164.9
  Top Layer w10: R32.2 C23.1@1067.7,2110 ; C23.1 RF3.2 ; RF3.2@1137.7,2100 Rflt3.1
NetC23_2: C23.2 C24.2 FDA1.3 R27.2 RF3.1 RI3.2 | length 685.9
  Top Layer w10: R27.2@680,2052.52 C24.2 764.8,2112.52 780.35,2128.07 FDA1.3@802.8,2128.07 ; R27.2@681.5,2047.01 RI3.2 1027.7,1990 C23.2 RF3.1
NetC24_1: C24.1 FDA1.4 | length 85.8
  Top Layer w10: C24.1 FDA1.4@800.67,2110.2
NetC25_1: C25.1 FDA1.1 | length 90.4
  Top Layer w10: C25.1@734.09,2235.83 FDA1.1@798.03,2171.89
NetC27_1: C27.1 R33.2 RF4.2 Rflt4.1 | length 164.9
  Top Layer w10: R33.2 C27.1@1067.7,2170 ; C27.1 RF4.2 ; RF4.2@1137.7,2180 Rflt4.1
NetC29_1: C29.1 Cflt3.1 R37.1 Rflt3.2 | length 170.8
  Top Layer w10: C29.1 Rflt3.2 ; C29.1@1261.24,2036.46 R37.1@1307.34,2036.46 ; R37.1@1316.2,2043.8 Cflt3.1
NetC30_1: C30.1 Cflt3.2 R36.1 Rflt4.2 | length 170.8
  Top Layer w10: Rflt4.2 C30.1 R36.1@1303.8,2240 ; Cflt3.2 R36.1@1316.2,2236.2
NetC32_1: C32.1 R10.2 | length 55.7
  Top Layer w10: R10.2@720.98,942.11 C32.1
NetC37_1: C37.1 R42.1 U4.1 | length 135.2
  Top Layer w20: U4.1@1023.27,1640 R42.1 C37.1
NetC37_2: C37.2 R43.1 U4.4 | length 350.6
  Top Layer w20: U4.4 988.46,1480 1110,1480 1151.5,1521.5 C37.2 R43.1@1208.5,1570
NetC39_1: C39.1 R44.2 R45.1 TP28.1 U4.3 | length 341.5
  Top Layer w20: R45.1@940,1688.5 1000,1688.5 R44.2@1060,1688.5 ; U4.3 R45.1@942.6,1685.91 ; R44.2@1072,1688.5 TP28.1@1192,1808.5
NetC41_1: C41.1 U3.4 | length 60.7
  Top Layer w20: 739.29,1561.5 C41.1
NetC42_2: C42.2 R47.1 | length 83.8
  Top Layer w20: C42.2 870,1602.91 R47.1
NetFDA1_10: FDA1.10 R32.1 | length 65.8
  Top Layer w10: FDA1.10 952.42,2130.16 R32.1
NetFDA1_11: FDA1.11 R33.1 | length 65.8
  Top Layer w10: FDA1.11 952.42,2149.84 R33.1
NetJ1_1: J1.1 R1.1 RI1.1 | length 447.3
  Top Layer w10: J1.1@350.31,1195.54 358.98,1204.21 464.58,1204.21 R1.1@558.19,1110.6 ; R1.1@559.69,1103.41 RI1.1
NetJ2_1: J2.1 R7.1 RI2.1 | length 449.9
  Top Layer w10: J2.1@347.67,612.88 356.34,604.21 464.58,604.21 R7.1@558.19,697.82 ; R7.1@559.69,703.41 RI2.1
NetJ3_1: J3.1 R19.2 | length 375.8
  Top Layer w10: R19.2 1387.85,1117.85 1490.89,1220.89 J3.1
NetJ4_1: J4.1 R20.2 | length 370.7
  Top Layer w10: R20.2 1388.37,911.63 1489.11,810.89 J4.1
NetJ6_1: J6.1 L1.1 | length 306.1
  Top Layer w80: J6.1@2160,1679.53 L1.1
NetJ7_1: J7.1 L2.1 | length 312.9
  Top Layer w80: L2.1 J7.1
NetJ12_1: J12.1 R21.1 RI3.1 | length 489.7
  Top Layer w10: J12.1@240,1860 263.31,1836.69 356.69,1836.69 440,1920 R21.1 ; R21.1@441.5,1990 RI3.1
NetJ13_1: J13.1 R24.1 RI4.1 | length 492
  Top Layer w10: J13.1@234.01,2413.39 257.32,2436.69 350.7,2436.69 434.01,2353.39 434.01,2290 RI4.1
NetJ14_1: J14.1 R36.2 | length 276.5
  Top Layer w10: R36.2 1363.62,2303.62 1411.87,2351.87 J14.1
NetJ15_1: J15.1 R37.2 | length 259.1
  Top Layer w10: R37.2 1363.62,1996.38 1418.13,1941.87 J15.1
NetR46_2: R46.2 U3.3 | length 92.5
  Top Layer w15: R46.2 702.8,1514.29 U3.3
V_CM_OPA: C33.1 C36.1 R38.1 R41.1 | length 183.2
  Top Layer w20: C33.1@1270,1508.14 R41.1 1305.12,1568.5 1315.12,1568.5 R38.1 ; C36.1 C33.1
V_CM_THS: FDA1.9 R41.2 R42.2 R43.2 TP29.1 | length 743.9
  Top Layer w10: FDA1.9 960,2065.59 v1(960,2030) ; v1(960,1950) 990,1920 1280,1920 1310,1890 TP29.1@1310,1700
  Bottom Layer w10: v1(960,1950) v1(960,2030)
V_REF_OPA: C34.1 C35.1 R38.2 R39.2 TP30.1 U1.3 U2.3 | length 1289.3
  Top Layer w10: v1(837.67,1222.88) 885.45,1222.88 U1.3 ; v3(857.32,812.88) 864.17,812.88 868.83,817.54 U2.3
  Top Layer w20: C35.1@1276.46,1390 C34.1 R39.2 ; R39.2@1330,1451.5 R38.2
  Bottom Layer w20: v1(837.67,1222.88) 924.78,1310 v1(1230,1310) ; v3(857.32,812.88) 857.32,897.32 1210,1250 v1(1230,1250)
VCC: C7.1 C8.1 C9.1 C38.2 C40.2 FDA1.5 FDA1.6 FDA1.7 FDA1.8 FDA1.12 L1.2 U1.6 U2.6 U3.1 U3.2 U4.5 | length 356.1
  Top Layer w10: U3.1@649.21,1570 U3.1 ; FDA1.12 985.59,2240 v1(1010,2240) ; U2.6 v1@1010.75,664.11
  Top Layer w15: U3.1 U3.2 ; 670.01,1545.35 664.39,1586.28 U3.2@671.31,1595.41
  Top Layer w20: v1(970,1060) U1.6@970,1104.86 ; U4.5@1020,1528.46 v1(1020,1570)
  other v1: 1018.43,664.11 600,1550 600,1580 830,2040 860,2040 890,2040 2159.76,2099.13 2159.76,2182.05 2150,2320 2185.3,2320 2149.3,2355.21
VEE: C10.1 C11.1 C12.1 FDA1.13 FDA1.14 FDA1.15 FDA1.16 L2.2 U1.2 U1.5 U2.2 U2.5 | length 365.3
  Top Layer w10: v3(887.67,1052.88) 907.19,1052.88 928.19,1073.88 U1.5 U1.2 ; v1(928.19,663.41) U2.5 U2.2 ; C11.1 C11.1@2094.06,723.48
  other v1: 2119.61,555.57 2164.78,565.89 2190,609.57 2140,660 2190,660 830,2240 860,2240 890,2240
VREF: C42.1 R45.2 U3.5 U3.6 | length 146.8
  Top Layer w10: U3.6 702.8,1772.8 750,1820
  Top Layer w15: U3.6 U3.5 757.6,1747.6
pads on no net: FID1.1 FID2.1 FID3.1

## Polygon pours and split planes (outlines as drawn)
GND on GND "GND" (solid, pour order 2): -0.18,2690 -0.18,-10 2480,-10 2480,2690
V_REF_OPA on Top Layer "Top Layer-No Net 6" (solid, pour order 56): 1215.04,1200 1350,1200 1350,1418.54 1215.04,1418.54
GND on Top Layer "Top Layer-No Net 10" (solid, pour order 54): 552.8,1670 620,1670 620,1720 670.08,1720 669.98,1784.02 584.02,1784.02 552.8,1752.8
VREF on Top Layer "Top Layer-No Net 9" (solid, pour order 52): 960,1720 960,1830 750,1830 715.49,1795.49 715.65,1719.13
VCC on Top Layer "Top Layer-No Net 8" (solid, pour order 50): 552.8,1650 619.13,1650 619.13,1600 673.09,1600 683.31,1589.78 690,1583.09 690,1532.11 590,1532.11 552.8,1569.31
GND on Top Layer "Top Layer-No Net 5" (solid, pour order 44): 979.82,1830 1060,1830 1080,1810 1080,1740 980.36,1740
GND on Top Layer "Top Layer-No Net 2" (solid, pour order 42): 900.57,1422.35 737.65,1422.35 730,1430 730,1497.65 744.45,1508.7 900.57,1508.19
V_CM_THS on Top Layer "Top Layer-No Net 1" (solid, pour order 40): 1328.2,1610 1170,1610 1141.3,1610 1130,1621.3 1130,1700 1186,1756 1327.66,1756
VEE on Top Layer "Top Layer-No Net" (solid, pour order 12): 2210.24,750 2160.58,750 2060.24,750 2060.24,649.66 2060.24,500.71 2150.24,500.71 2210.24,560.71
VCC on Top Layer "VCC" (solid, pour order 8): 2065.55,2066.14 2213.94,2066.14 2213.94,2310.15 2150,2374.09 2065.55,2374.09
VCC on Top Layer "Top Layer-No Net 3" (solid, pour order 26): 820,2100 900,2100 900,2030 870,2000 840,2000 820,2020
VEE on Top Layer "Top Layer-No Net 4" (solid, pour order 28): 804.34,2182.32 910.54,2182.32 910.54,2253.7 910.54,2270 902.06,2278.47 890.27,2290.27 860,2290.27 804.34,2290.27
VCC on Power "Power-No Net 1" (solid, pour order 34): 2460,2650 990,2650 990,2190 580,2190 580,1411.88 980,1011.88 980,620 1030,620 1220,810 2460,810
VEE on Power "Power-No Net 4" (solid, pour order 38): 2460,780 2460,40 40,40 40,2650 960,2650 960,2220 560,2220 560,1398.17 950,1008.17 950,590 1040,590 1230,780

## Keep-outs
Keep-Out Layer:
  text ".Layer_Name" at 577,-858.49 h60

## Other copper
Top Layer:
  text ".Layer_Name" at 577,-858.49 h60
Bottom Layer:
  text ".Layer_Name" at 577,-858.49 h60

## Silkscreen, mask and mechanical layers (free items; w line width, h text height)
Top Overlay:
  text ".Layer_Name" at 577,-858.49 h60
Bottom Overlay:
  text ".Layer_Name" at 577,-858.49 h60
Top Paste:
  text ".Layer_Name" at 577,-858.49 h60
Bottom Paste:
  text ".Layer_Name" at 577,-858.49 h60
Top Solder:
  text ".Layer_Name" at 577,-858.49 h60
  text ".Layer_Name" at 577,-858.49 h60
Bottom Solder:
  text ".Layer_Name" at 577,-858.49 h60
Drill Guide:
  text ".Layer_Name" at 577,-858.49 h60
M1 Board Outline:
  the board outline again, w10
  text ".Layer_Name" at 577,-858.49 h60
M2 Board Dimensions:
  rectangle: 0,-275 125,-150
  rectangle: 125,-400 500,-275
  lines w7: 0,-275 1000,-275 ; 125,-400 125,-150 ; 250,-400 250,-150 ; 500,-400 500,-150 ; 750,-400 750,-150 ; 0,-400 1000,-400 1000,-150 0,-150 0,-400
  text ".Layer_Name" at 577,-858.49 h60
M3 3D STEP Top:
  text ".Layer_Name" at 577,-858.49 h60
M4 3D STEP Bottom:
  text ".Layer_Name" at 577,-858.49 h60
M5 Assembly Top:
  lines w10: -292,-930.17 6308,-930.17 ; -292,-726.83 6310,-726.83 ; -292,-523.5 -292,-1133.5 3713,-1133.5 6310,-1133.5 6310,-523.5 -291.5,-523.5 -291.5,-1133.5 1284,-1133.5 ; 2173,-1133.5 2173,-523.5 ; 3440,-726.83 3440,-523.5 ; 4280,-726.83 4280,-523.5 ; 4902,-1140 4902,-937.17
  text "COMPONENTS MARKED 'DNP' SHOULD NOT BE POPULATED." at 1153.5,-318.5 h60
  text "ASSEMBLY VARIANT:" at 1153,-434 h60
  text ".VariantName" at 2189,-434 h60
  text "PCB VIEWED FROM TOP SIDE" at -228.5,-655.67 h60
  text "BOARD #:" at 2248,-655.67 h60
  text ".PRJ_Number" at 2793.5,-655.67 h60
  text "REV:" at 3638,-655.67 h60
  text ".PCB_Rev" at 3929.5,-655.67 h60
  text "SVN REV:" at 4476,-655.67 h60
  text ".VersionControl_RevNumber" at 4982,-655.67 h60
  text "TID #:" at 2248,-859 h60
  text ".TID" at 2793.5,-859 h60
  text "PLOT NAME =" at -228.5,-1064.34 h60
  text ".plot_File_Name" at 577,-1064.34 h60
  text "GENERATED    :" at 2250,-1064.34 h60
  text ".Print_Date" at 3119.5,-1064.34 h60
  text ".Print_Time" at 3848.5,-1064.34 h60
  text "TEXAS INSTRUMENTS" at 5113,-1064.34 h60
M6 Assembly Bottom:
  lines w10: -292.5,-727.33 6309.5,-727.33 ; -290.5,-930.67 6309.5,-930.67 ; 1115.5,-1140.5 1115.5,-937.67 ; 1737.5,-727.33 1737.5,-524 ; 2577.5,-727.33 2577.5,-524 ; 3844.5,-1134 3844.5,-524 ; 4733.5,-1134 6309,-1134 6309,-524 -292.5,-524 -292.5,-1134 2304.5,-1134 6309.5,-1134 6309.5,-524
  text "COMPONENTS MARKED 'DNP' SHOULD NOT BE POPULATED." at 6102,-318 h60
  text ".VariantName" at 5058,-434 h60
  text "ASSEMBLY VARIANT:" at 6097,-434 h60
  text ".VersionControl_RevNumber" at 1035.5,-656.17 h60
  text "SVN REV:" at 1541.5,-656.17 h60
  text ".PCB_Rev" at 2088,-656.17 h60
  text "REV:" at 2379.5,-656.17 h60
  text ".PRJ_Number" at 3224,-656.17 h60
  text "BOARD #:" at 3769.5,-656.17 h60
  text "PCB VIEWED FROM BOTTOM SIDE" at 6246,-656.17 h60
  text ".TID" at 3224,-859.5 h60
  text "TID #:" at 3769.5,-859.5 h60
  text "TEXAS INSTRUMENTS" at 904.5,-1064.84 h60
  text ".Print_Time" at 2169,-1064.84 h60
  text ".Print_Date" at 2898,-1064.84 h60
  text "GENERATED    :" at 3767.5,-1064.84 h60
  text ".plot_File_Name" at 5440.5,-1064.84 h60
  text "PLOT NAME =" at 6246,-1064.84 h60
M9 Title Sheet:
  drawing of 57 lines, arcs and shapes, not listed
  text "1" at 739.84,8036.5 h70
  text "2" at 3235.5,8036.5 h70
  text "3" at 5724.84,8036.5 h70
  text "4" at 8231.51,8036.5 h70
  text "5" at 10730.5,8036.5 h70
  text "6" at 13235.5,8036.5 h70
  text "A" at -416.5,6893.5 h70
  text "A" at 14383.5,6893.5 h70
  text "B" at -416.5,4513.5 h70
  text "B" at 14383.5,4513.5 h70
  text "C" at -416.5,2138.5 h70
  text "C" at 14383.5,2138.5 h70
  text "PROJECT TITLE:" at 11343.5,277.5 h45
  text ".PRJ_Title" at 11393.5,144.17 h70
  text "DESIGNED FOR:" at 11343.5,-23.5 h45
  text ".PRJ_Customer" at 11393.5,-163.5 h70
  text "D" at -416.5,-231.5 h70
  text "D" at 14383.5,-231.5 h70
  text "FILE NAME:" at 11343.5,-323.5 h45
  text ".PCB_File_Name_No_Path" at 11393.5,-443.5 h70
  text "Texas Instruments (TI) and/or its licensors do not warrant the accuracy or completeness of this specification" at 6374,-605.34 h45
  text "ENGINEER:" at 11343.5,-613.5 h45
  text "LAYOUT BY:" at 12848.5,-613.5 h45
  text "or any information contained therein. TI and/or its licensors do not warrant that this design will meet" at 6329.01,-718 h45
  text ".PRJ_Engineer" at 11393.5,-768.49 h70
  text ".PCB_Layout" at 12899,-768.49 h70
  text "the specifications, will be suitable for your application or fit for any particular purpose, or will operate in" at 6329.01,-830.67 h45
  text ".Layer_Name" at 577,-858.49 h60
  text "ALTIUM DESIGNER VERSION:" at 12848.5,-923.5 h45
  text "an implementation. TI and/or its licensors do not warrant that the design is production worthy. You should" at 6329.01,-943.33 h45
  text "completely validate and test your design implementation to confirm the system functionality for your application." at 6374,-1056 h45
  text ".print_Scale" at 11393.5,-1056.83 h70
  text ".Application_BuildNumber" at 12899,-1056.83 h70
  text "1" at 739.84,-1263.5 h70
  text "2" at 3235.5,-1263.5 h70
  text "3" at 5724.84,-1263.5 h70
  text "4" at 8231.51,-1263.5 h70
  text "5" at 10730.5,-1263.5 h70
  text "6" at 13235.5,-1263.5 h70
M10 Fab Notes:
  drawing of 173 lines, arcs and shapes, not listed
  text "DESIGN INFORMATION" at 12378.02,6201 h60
  text "MIN. TRACK WIDTH:" at 11733.46,6021 h60
  text "8" at 12829.7,6021 h60
  text "MIL" at 12984.46,6021 h60
  text "MIN. CLEARANCE:" at 11733.46,5889 h60
  text "0.2" at 12769.7,5889 h60
  text "mm" at 12984.46,5889 h60
  text "MIN. VIA PAD SIZE:" at 11733.46,5757 h60
  text "24" at 12799.71,5757 h60
  text "MIL" at 12984.46,5757 h60
  text "0.05mm (2MIL)" at 12428.46,5615.29 h60
  text "MINIMUM ANNULAR RING" at 11404.23,5611 h60
  text "EXTERNAL" at 13136.46,5611 h60
  text "PER" at 11604.23,5493 h60
  text "IPC-D-275 CLASS 2 LEVEL C" at 11824.23,5493 h60
  text "MIL, HOLES" at 13312.46,5380.71 h60
  text "+/-" at 12920,5380 h60
  text "+/-" at 13774,5380 h60
  text "REGISTRATION TOLERANCES:" at 11404.23,5375 h60
  text "METAL" at 12604,5375 h60
  text "5" at 13180.2,5375 h60
  text "3" at 14013.2,5375 h60
  text "MIL" at 14129.46,5375 h60
  text "+/-" at 13774,5262 h60
  text "HOLE SIZE TOLERANCE (UNLESS OTHERWISE SPECIFIED):" at 11404.23,5257 h60
  text "3" at 14013.2,5257 h60
  text "MIL" at 14129.46,5257 h60
  text "MATERIAL:" at 11329.46,5047.54 h60
  text "FR-4 High Tg" at 12315.9,4907.21 h60
  text "FR-408" at 11750.46,4898.64 h60
  text "OTHER" at 13238.46,4898.64 h60
  text "X" at 12161,4895 h60
  text "62 MIL (1.6mm) +/-10%" at 12070.56,4735.92 h60
  text "THICKNESS:" at 11404.23,4731.64 h60
  text "X" at 11942.4,4731.64 h60
  text "OTHER" at 13355.46,4731.64 h60
  text "TOLERANCE:" at 11404.23,4573.64 h60
  text "X" at 12243.53,4573.64 h60
  text "ANSI IPC-6012 TYPE 3 CLASS 2" at 12430.48,4573.64 h60
  text "OTHER +/-" at 12430.46,4417.64 h60
  text "BOW & TWIST:" at 11404.23,4260.64 h60
  text "X" at 12243.53,4260.64 h60
  text "ANSI IPC-6012 TYPE 3 CLASS 2" at 12430.48,4260.64 h60
  text "OTHER +/-" at 12430.46,4102.13 h60
  text "DRILLING:" at 11329.46,3963.64 h60
  text "REFERENCE:" at 11404.23,3846.64 h60
  text "X" at 12052.46,3846.64 h60
  text "AS SHOWN" at 12239.46,3846.64 h60
  text "X" at 12953.46,3846.64 h60
  text "NC_DRILL FILES" at 13090.46,3846.64 h60
  text "PTH COPPER THICKNESS:" at 11404.23,3688.64 h60
  text "X" at 12534.46,3688.64 h60
  text "20-30 um" at 12671.46,3688.64 h60
  text "OTHER" at 13388.46,3688.64 h60
  text "BOARD FINISH:" at 11329.46,3529.64 h60
  text "SILKSCREEN:" at 11484.68,3411.64 h60
  text "X" at 12433.46,3411.64 h60
  text "TOP" at 12559.46,3411.64 h60
  text "X" at 12943.46,3411.64 h60
  text "BOTTOM" at 13070.46,3411.64 h60
  text "SILKSCREEN COLOR:" at 11484.68,3244.64 h60
  text "X" at 12432.42,3244.64 h60
  text "WHITE" at 12559.46,3244.64 h60
  text "OTHER" at 13070.46,3244.64 h60
  text "X" at 12563.42,3085.44 h60
  text "GREEN" at 12690.46,3085.44 h60
  text "OTHER" at 13308.46,3085.44 h60
  text "SOLDER RESIST COLOR:" at 11484.68,3074.64 h60
  text "X" at 12563.42,2915.44 h60
  text "MATTE" at 12690.46,2915.44 h60
  text "SEMI-GLOSS" at 13308,2914.8 h60
  text "IMMERSION GOLD (ENIG)" at 12390.46,2726.92 h60
  text "ENEPIG" at 13728,2723.64 h60
  text "SURFACE FINISH:" at 11329.46,2722.64 h60
  text "X" at 12203.51,2722.64 h60
  text "IMM. TIN/SILVER OR EQUIV" at 11659,2565.64 h60
  text "OTHER" at 13090.46,2565.64 h60
  text "ARRAY/PANEL:" at 11329.46,2386.64 h60
  text "CUT AND TRIM PER M1 BOARD OUTLINE" at 12390.46,2382.35 h60
  text "N.C. ROUTE" at 12390.46,2230.64 h60
  text "X" at 13069.46,2230.64 h60
  text "V. SCORE" at 13256.46,2230.64 h60
  text "CERTIFICATION:" at 11329.46,2093.64 h60
  text "MATERIALS AND WORKMANSHIP FOR ALL PCBS" at 12054.46,2093.64 h60
  text "TO MEET OR EXCEED THE REQUIREMENTS OF:" at 12054.46,1995.64 h60
  text "X" at 11680.96,1859.13 h60
  text "ANSI IPC-A-600F CLASS ->" at 11819.96,1859.13 h60
  text "X" at 13459.02,1859.13 h60
  text "2" at 13577.96,1859.14 h60
  text "1" at 13262.96,1857.64 h60
  text "3" at 13931.96,1857.64 h60
  text "X" at 12495.02,1699.64 h60
  text "RoHS" at 12631.96,1699.64 h60
  text "OTHER" at 13276.36,1699.64 h60
  text "PER ORDER" at 13673.42,1699.64 h60
  text "ALL BOARDS MUST MEET OR EXCEED UL94-V0 REQUIREMENTS." at 11357,1534 h60
  text "PCB MUST BEAR THE UL94V-0 UL REGISTERED MATERIAL ID NUMBER" at 11357,1414 h60
  text "ADDITIONAL REQUIREMENTS:" at 11329.46,1240.64 h60
  text "MICROSECTION:" at 11404.23,1125.64 h60
  text "YES" at 12309.96,1125.64 h60
  text "REQUIRED" at 13171.46,969.49 h60
  text "BARE BOARD ELEC. TEST:" at 11404.23,966.64 h60
  text "NONE" at 12709.96,966.64 h60
  text "X" at 13044.46,966.64 h60
  text "PER ORDER" at 13763.46,966.64 h60
  text ".Layer_Name" at 577,-858.49 h60
M11 Gerber Information:
  lines w10: -292,-930.17 6308,-930.17 ; -292,-726.83 6310,-726.83 ; -292,-523.5 -292,-1133.5 3713,-1133.5 6310,-1133.5 6310,-523.5 -291.5,-523.5 -291.5,-1133.5 1284,-1133.5 ; 2173,-1133.5 2173,-523.5 ; 3440,-726.83 3440,-523.5 ; 4280,-726.83 4280,-523.5 ; 4902,-1140 4902,-937.17
  text "ALL ARTWORK VIEWED FROM TOP SIDE" at -228.5,-655.67 h60
  text "BOARD #:" at 2248,-655.67 h60
  text ".PRJ_Number" at 2793.5,-655.67 h60
  text "REV:" at 3638,-655.67 h60
  text ".PCB_Rev" at 3929.5,-655.67 h60
  text "SVN REV:" at 4476,-655.67 h60
  text ".VersionControl_RevNumber" at 4982,-655.67 h60
  text "LAYER NAME =" at -228.5,-858.49 h60
  text "TID #:" at 2248,-859 h60
  text ".TID" at 2793.5,-859 h60
  text "PLOT NAME =" at -228.5,-1064.34 h60
  text ".plot_File_Name" at 577,-1064.34 h60
  text "GENERATED    :" at 2250,-1064.34 h60
  text ".Print_Date" at 3119.5,-1064.34 h60
  text ".Print_Time" at 3848.5,-1064.34 h60
  text "TEXAS INSTRUMENTS" at 5113,-1064.34 h60
M12 Stackup:
  drawing of 191 lines, arcs and shapes, not listed
  text "Layer" at 9790.34,7830 h60
  text "Name" at 10200.26,7830 h60
  text "Material" at 11130,7830 h60
  text "Thickness" at 11989.77,7830 h60
  text "Constant" at 12639.6,7830 h60
  text "Board Layer Stack" at 13209.46,7830 h60
  text "1" at 9790.34,7710 h60
  text "Top Overlay" at 10200.26,7710 h60
  text "2" at 9790.34,7590 h60
  text "Top Solder" at 10200.26,7590 h60
  text "Solder Resist" at 11130,7590 h60
  text "0.40mil" at 11989.77,7590 h60
  text "3.5" at 12639.6,7590 h60
  text "3" at 9790.34,7470 h60
  text "Top Layer" at 10200.26,7470 h60
  text "Copper" at 11130,7470 h60
  text "1.40mil" at 11989.77,7470 h60
  text "4" at 9790.34,7350 h60
  text "Dielectric1" at 10200.26,7350 h60
  text "FR-4" at 11130,7350 h60
  text "59.20mil" at 11989.77,7350 h60
  text "4.8" at 12639.6,7350 h60
  text "5" at 9790.34,7230 h60
  text "Bottom Layer" at 10200.26,7230 h60
  text "Copper" at 11130,7230 h60
  text "1.40mil" at 11989.77,7230 h60
  text "6" at 9790.34,7110 h60
  text "Bottom Solder" at 10200.26,7110 h60
  text "Solder Resist" at 11130,7110 h60
  text "0.40mil" at 11989.77,7110 h60
  text "3.5" at 12639.6,7110 h60
  text "7" at 9790.34,6990 h60
  text "Bottom Overlay" at 10200.26,6990 h60
  text ".Layer_Name" at 577,-858.49 h60
M13 Component Bodies Top:
  text ".Layer_Name" at 577,-858.49 h60
M14 Component Bodies Bottom:
  text ".Layer_Name" at 577,-858.49 h60
M15 Courtyards Top:
  text ".Layer_Name" at 577,-858.49 h60
M16 Courtyards Bottom:
  text ".Layer_Name" at 577,-858.49 h60
Drill Drawing:
  lines w10: 5336.16,2864.85 5391.49,2864.85 5391.49,2920.18 5336.16,2920.18 5336.16,2864.85 ; 5336.16,3003.18 5349.99,3003.18 5363.82,2989.35 5377.66,3003.18 5391.49,3003.18 5377.66,3017.02 5391.49,3030.85 5377.66,3030.85 5363.82,3044.68 5349.99,3030.85 5336.16,3030.85 5349.99,3017.02 5336.16,3003.18 ; 5336.16,3113.85 5363.82,3127.68 5391.49,3113.85 5377.66,3141.52 5391.49,3169.18 5363.82,3155.35 5336.16,3169.18 5349.99,3141.52 5336.16,3113.85 ; 5336.16,3252.18 5349.99,3252.18 5349.99,3238.35 5377.66,3238.35 5377.66,3252.18 5391.49,3252.18 5391.49,3279.85 5377.66,3279.85 5377.66,3293.68 5349.99,3293.68 5349.99,3279.85 5336.16,3279.85 5336.16,3252.18
  lines w12: 5286,2827.5 8518.19,2827.5 ; 5286,3325.5 8518.19,3325.5 ; 5624.01,2703 5624.01,3450 ; 5956.17,2703 5956.17,3450 ; 6592.65,2703 6592.65,3450 ; 6851.85,2703 6851.85,3450 ; 7227.09,2703 7227.09,3450 ; 7951.64,2703 7951.64,3450 ; 5286,2703 8518.19,2703 8518.19,3450 5286,3450 5286,2703
  text "Symbol" at 5360.7,3362.85 h72
  text "Quantity" at 5661.36,3362.85 h72
  text "Finished Hole Size" at 5993.52,3362.85 h72
  text "Plated" at 6630,3362.85 h72
  text "Hole Type" at 6889.2,3362.85 h72
  text "Drill Layer Pair" at 7264.44,3362.85 h72
  text "Hole Tolerance" at 7988.99,3362.85 h72
  text "7" at 5661.36,3238.35 h60
  text "7.87mil (0.200mm)" at 5993.52,3238.35 h60
  text "PTH" at 6630,3238.35 h60
  text "Round" at 6889.2,3238.35 h60
  text "Top Layer - Bottom Layer" at 7264.44,3238.35 h60
  text "57" at 5661.36,3113.85 h60
  text "10.00mil (0.254mm)" at 5993.52,3113.85 h60
  text "PTH" at 6630,3113.85 h60
  text "Round" at 6889.2,3113.85 h60
  text "Top Layer - Bottom Layer" at 7264.44,3113.85 h60
  text "48" at 5661.36,2989.35 h60
  text "28.00mil (0.711mm)" at 5993.52,2989.35 h60
  text "PTH" at 6630,2989.35 h60
  text "Round" at 6889.2,2989.35 h60
  text "Top Layer - Bottom Layer" at 7264.44,2989.35 h60
  text "3" at 5661.36,2864.85 h60
  text "270.00mil (6.858mm)" at 5993.52,2864.85 h60
  text "PTH" at 6630,2864.85 h60
  text "Round" at 6889.2,2864.85 h60
  text "Top Layer - Bottom Layer" at 7264.44,2864.85 h60
  text "115 Total" at 5661.36,2740.35 h60
  text ".Layer_Name" at 577,-858.49 h60
M17 Embedded Cavity:
  text ".Layer_Name" at 577,-858.49 h60
M18 Embedded Assembly:
  text ".Layer_Name" at 577,-858.49 h60
M19 Embedded Keepout:
  text ".Layer_Name" at 577,-858.49 h60

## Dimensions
0,-400 to 1000,-400 on M2 Board Dimensions
0,0 to 0.05,2690 on M2 Board Dimensions
0,0 to 2499.89,0 on M2 Board Dimensions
